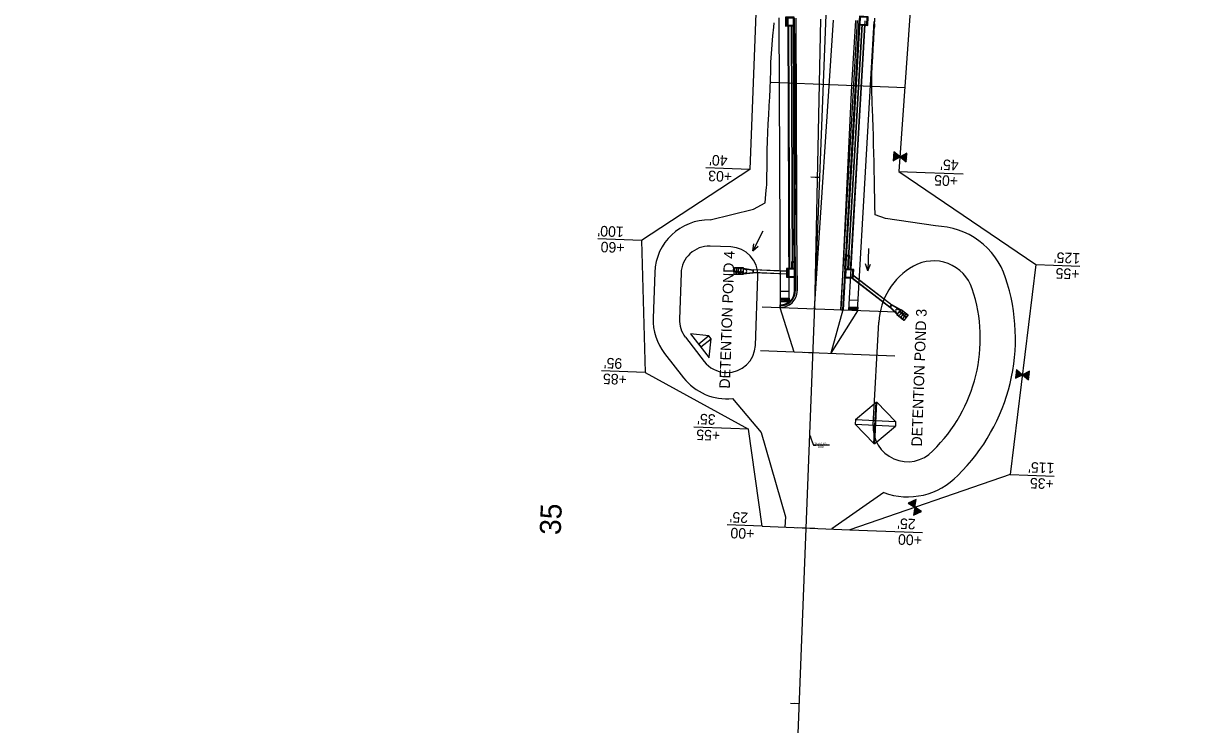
# Model space of a CAD drawing. Extents: x 670017 to 673226, y 705371 to 707498.
# Drawn here: x 671255 to 671926, y 705770 to 706170 of the extents above; entities that cross this region are included whole.
import ezdxf

# ---------------------------------------------------------------- set-up
doc = ezdxf.new("R2010")
doc.units = 0
for name, color, linetype in [('C-STRM-STRC', 7, 'Continuous'), ('EL L SCBV', 7, 'Continuous'), ('EL R SCBV', 7, 'Continuous'), ('R_Drainage Flow Lines', 7, 'Continuous'), ('R_Drainage Stage 1A', 7, 'Continuous'), ('R_Drainage Stage 2', 7, 'Continuous'), ('R_Drainage Stage 2A', 7, 'Continuous'), ('R_Fence', 7, 'Continuous'), ('R_Horz Alg', 7, 'Continuous'), ('R_Horz Alg Station', 7, 'Continuous'), ('R_Horz Alg Station Annot', 7, 'Continuous'), ('R_No Plot', 7, 'Continuous'), ('R_No Plot FOC', 7, 'Continuous'), ('R_Proposed Const Limits Stage 2', 7, 'Continuous'), ('R_Proposed Const Limits Stage 2A', 7, 'Continuous'), ('R_Proposed Road Stage 2', 7, 'Continuous'), ('R_Proposed Road Stage 2A', 7, 'Continuous'), ('R_Proposed Shoulder Stage 2', 7, 'Continuous'), ('R_Proposed Sidewalk Stage 2', 7, 'Continuous'), ('R_Proposed Sidewalk Stage 2A', 7, 'Continuous'), ('R_ROW', 7, 'Continuous'), ('R_ROW Annot', 7, 'Continuous'), ('R_Striping', 7, 'Continuous'), ('R_Water Annot', 7, 'Continuous')]:
    doc.layers.add(name, color=color, linetype=linetype)

# ---------------------------------------------------------------- blocks, each defined once
blk = doc.blocks.new('FLOW ARROW')
at = {"layer": 'R_Water Annot'}
for p, q in [((-12.57, 0), (0, 0)), ((0, 0), (-3.85, 1.4)), ((0, 0), (-3.85, -1.4))]:
    blk.add_line(p, q, dxfattribs=at)
blk = doc.blocks.new('POND 3 STRC')
at = {"layer": 'C-STRM-STRC'}
for points in [[(2047630.3, 2151508), (2047666.7, 2151537.5), (2047668.2, 2151537.4), (2047700.2, 2151503.1)], [(2047661.7, 2151465.8), (2047666.7, 2151537.5)], [(2047663.2, 2151465.7), (2047668.2, 2151537.4)], [(2047630.3, 2151508), (2047629.7, 2151500.1)], [(2047630.3, 2151508), (2047700.2, 2151503.1)], [(2047629.7, 2151500.1), (2047699.7, 2151495.2)], [(2047629.7, 2151500.1), (2047661.7, 2151465.8), (2047663.2, 2151465.7), (2047699.7, 2151495.2)], [(2047700.2, 2151503.1), (2047699.7, 2151495.2)]]:
    blk.add_lwpolyline(points, dxfattribs=at)

msp = doc.modelspace()

# ---------------------------------------------------------------- linework, layer by layer
at = {"layer": 'EL L SCBV'}
msp.add_line((671694.44, 706172.8), (671696.1, 706017.44), dxfattribs=at)
msp.add_arc((671686.6, 706017.49), 9.5, 267.78251, 359.69166, dxfattribs=at)
at = {"layer": 'EL R SCBV'}
for p, q in [((671729.41, 706171.45), (671727.09, 706134.51)), ((671727.09, 706134.51), (671721.03, 706006.65))]:
    msp.add_line(p, q, dxfattribs=at)
at = {"layer": 'R_Drainage Stage 1A'}
for points in [[(671723.31, 706029.87), (671723.69, 706037.86), (671725.68, 706037.76), (671725.31, 706029.77)], [(671723.81, 706029.84), (671724.16, 706037.34), (671725.16, 706037.29), (671724.81, 706029.8)]]:
    msp.add_lwpolyline(points, close=True, dxfattribs=at)
at = {"layer": 'R_Drainage Stage 2'}
for p, q in [((671732.88, 706169.31), (671724.71, 706029.3)), ((671733.05, 706169.3), (671724.88, 706029.29)), ((671734.54, 706169.23), (671726.38, 706029.22)), ((671734.71, 706169.22), (671726.54, 706029.21)), ((671726.68, 706025.2), (671748.93, 706008.08)), ((671726.97, 706025.19), (671749.03, 706008.21)), ((671727.66, 706026.56), (671749.95, 706009.4)), ((671727.67, 706026.76), (671750.05, 706009.53)), ((671748.93, 706008.08), (671749.05, 706008.24)), ((671753.1, 706003.96), (671748.93, 706008.08)), ((671749.05, 706008.24), (671749.93, 706009.37)), ((671749.05, 706008.24), (671749.24, 706008.09)), ((671749.24, 706008.09), (671750.11, 706009.23)), ((671753.22, 706004.12), (671749.25, 706008.11)), ((671749.93, 706009.37), (671750.05, 706009.53)), ((671749.93, 706009.37), (671750.11, 706009.23)), ((671755.1, 706006.55), (671750.05, 706009.53)), ((671754.97, 706006.39), (671750.1, 706009.21)), ((671753.22, 706004.12), (671752.35, 706005.46)), ((671752.35, 706005.46), (671753.1, 706003.96)), ((671753.22, 706004.12), (671753.1, 706003.96)), ((671753.22, 706004.12), (671753.1, 706003.96)), ((671753.22, 706004.12), (671754.97, 706006.39)), ((671754.97, 706006.39), (671753.45, 706006.89)), ((671753.45, 706006.89), (671755.1, 706006.55)), ((671754.97, 706006.39), (671755.1, 706006.55)), ((671754.97, 706006.39), (671755.1, 706006.55))]:
    msp.add_line(p, q, dxfattribs=at)
for points in [[(671736.28, 706168.64), (671736.53, 706173.63), (671731.54, 706173.88), (671731.29, 706168.89)], [(671735.81, 706169.16), (671736.01, 706173.16), (671732.01, 706173.36), (671731.81, 706169.36)], [(671728.07, 706024.64), (671728.3, 706029.63), (671723.31, 706029.87), (671723.07, 706024.87)], [(671727.59, 706025.16), (671727.78, 706029.16), (671723.78, 706029.34), (671723.59, 706025.35)], [(671752.88, 706003.67), (671755.32, 706006.84), (671759.28, 706003.79), (671756.84, 706000.62)]]:
    msp.add_lwpolyline(points, close=True, dxfattribs=at)
msp.add_lwpolyline([(671739.47, 705941.12), (671742.62, 705999.64)], dxfattribs=at)
for centre, radius, start, end in [((671773.79, 706011.23), 23.26, 18.3972, 119.59101), ((671781.56, 705997.54), 39, 119.59101, 176.9246), ((671711.08, 705990.37), 89.35, 314.20485, 18.3972), ((671753.15, 706005.98), 0.957, 71.80174, 213.02684), ((671759.03, 705939.68), 19.61, 175.79284, 317.04539)]:
    msp.add_arc(centre, radius, start, end, dxfattribs=at)
for centre in [(671754.2, 706004.36), (671755.2, 706003.55)]:
    msp.add_ellipse(centre, major_axis=(0.788, 0.971), ratio=0.517889, dxfattribs=at)
for centre, start_param, end_param in [((671755.77, 706006.3), 1.465244, 4.8447), ((671756.13, 706002.63), 3.535072, 9.058057), ((671756.78, 706005.49), 1.438249, 4.871695), ((671757.14, 706001.81), 5.467768, 8.991439), ((671757.14, 706001.81), 3.601691, 4.056701), ((671757.71, 706004.57), 1.309554, 5.00039), ((671758.71, 706003.76), 1.281641, 3.914409)]:
    msp.add_ellipse(centre, major_axis=(0.788, 0.971), ratio=0.517889, start_param=start_param, end_param=end_param, dxfattribs=at)
at = {"layer": 'R_Drainage Stage 2A'}
for p, q in [((671691.04, 706168.81), (671691.63, 706029.67)), ((671691.21, 706168.81), (671691.8, 706029.67)), ((671692.71, 706168.82), (671693.3, 706029.68)), ((671692.88, 706168.82), (671693.47, 706029.68)), ((671665.32, 706030.09), (671665.28, 706027.22)), ((671665.28, 706027.22), (671670.87, 706027.88)), ((671665.28, 706027.22), (671666.8, 706027.74)), ((671666.8, 706027.74), (671665.28, 706027.03)), ((671665.28, 706027.03), (671671.11, 706027.66)), ((671665.32, 706030.09), (671665.33, 706030.29)), ((671665.32, 706030.09), (671665.33, 706030.29)), ((671665.32, 706030.09), (671670.89, 706029.28)), ((671665.32, 706030.09), (671666.83, 706029.54)), ((671665.33, 706030.29), (671671.13, 706029.49)), ((671666.83, 706029.54), (671665.33, 706030.29)), ((671670.89, 706029.3), (671670.87, 706027.86)), ((671671.11, 706027.86), (671670.87, 706027.86)), ((671671.13, 706029.29), (671670.89, 706029.3)), ((671671.13, 706029.29), (671671.11, 706027.86)), ((671671.11, 706027.86), (671671.11, 706027.66)), ((671690.56, 706027.01), (671671.11, 706027.83)), ((671690.56, 706026.84), (671671.11, 706027.66)), ((671671.13, 706029.49), (671671.13, 706029.29)), ((671690.56, 706028.68), (671671.13, 706029.49)), ((671690.56, 706028.51), (671671.13, 706029.33)), ((671665.28, 706027.22), (671665.28, 706027.03)), ((671665.28, 706027.22), (671665.28, 706027.03))]:
    msp.add_line(p, q, dxfattribs=at)
for points in [[(671689.44, 706173.3), (671689.47, 706168.3), (671694.46, 706168.33), (671694.44, 706173.33)], [(671689.94, 706172.8), (671689.96, 706168.8), (671693.96, 706168.82), (671693.94, 706172.82)], [(671665.33, 706030.66), (671665.27, 706026.66), (671660.27, 706026.73), (671660.33, 706030.73)], [(671690.05, 706030.17), (671690.07, 706025.17), (671695.07, 706025.19), (671695.05, 706030.19)], [(671690.55, 706029.67), (671690.57, 706025.67), (671694.57, 706025.69), (671694.55, 706029.69)], [(671693.05, 706030.18), (671693.03, 706034.18), (671695.03, 706034.19), (671695.05, 706030.19)], [(671693.55, 706030.18), (671693.53, 706033.68), (671694.53, 706033.69), (671694.55, 706030.19)]]:
    msp.add_lwpolyline(points, close=True, dxfattribs=at)
for points in [[(671658.29, 706042.42), (671646.51, 706042.84)], [(671629.96, 706027.41), (671629.05, 706001.38)], [(671672.33, 705986.38), (671673.71, 706025.87)], [(671632.4, 705991.02), (671643.14, 705977.16)], [(671645.91, 705979.6), (671647.1, 705990.14), (671645.88, 705991.72), (671635.31, 705992.89)], [(671635.31, 705992.89), (671645.91, 705979.3)], [(671645.88, 705991.72), (671640.01, 705987.04), (671640.62, 705986.25), (671641.24, 705985.46), (671647.1, 705990.14), (671645.88, 705991.72)], [(671655.23, 705970.97), (671655.78, 705970.95)]]:
    msp.add_lwpolyline(points, dxfattribs=at)
for centre, radius, start, end in [((671645.95, 706026.85), 16, 87.99183, 177.99183), ((671657.72, 706026.43), 16, 357.99183, 87.99183), ((671666.5, 706028.64), 0.957, 288.56219, 69.7873), ((671645.04, 706000.82), 16, 177.99183, 217.7949), ((671656.34, 705986.94), 16, 267.99183, 357.99183), ((671655.79, 705986.96), 16, 217.7949, 267.99183)]:
    msp.add_arc(centre, radius, start, end, dxfattribs=at)
for centre, start_param, end_param in [((671660.71, 706027.1), 1.281641, 3.914409), ((671660.81, 706029.6), 5.467768, 8.991439), ((671660.81, 706029.6), 3.601691, 4.056701), ((671662, 706027.05), 1.309554, 5.00039), ((671662.1, 706029.54), 3.535072, 9.058057), ((671663.3, 706026.87), 1.438249, 4.871695), ((671664.59, 706026.82), 1.465244, 4.8447)]:
    msp.add_ellipse(centre, major_axis=(-0.05, -1.25), ratio=0.517889, start_param=start_param, end_param=end_param, dxfattribs=at)
for centre in [(671663.4, 706029.37), (671664.69, 706029.32)]:
    msp.add_ellipse(centre, major_axis=(-0.05, -1.25), ratio=0.517889, dxfattribs=at)
at = {"layer": 'R_Fence'}
for p, q in [((671751.03, 706094.82), (671752.81, 706092.7)), ((671751.09, 706095.53), (671753.26, 706092.94)), ((671751.15, 706096.23), (671753.71, 706093.19)), ((671752.28, 706095.67), (671754.15, 706093.43)), ((671756.84, 706094.91), (671758.4, 706093.04)), ((671757.28, 706095.15), (671758.46, 706093.75)), ((671757.73, 706095.4), (671758.53, 706094.45)), ((671758.18, 706095.64), (671758.59, 706095.16)), ((671758.63, 706095.89), (671758.65, 706095.86)), ((671750.78, 706092.01), (671751.03, 706091.72)), ((671750.85, 706092.71), (671751.47, 706091.96)), ((671750.91, 706093.41), (671751.92, 706092.21)), ((671750.97, 706094.12), (671752.37, 706092.45)), ((671754.27, 706094.08), (671754.6, 706093.68)), ((671755.05, 706093.93), (671756.26, 706092.48)), ((671755.5, 706094.17), (671758.22, 706090.93)), ((671755.94, 706094.42), (671758.28, 706091.63)), ((671756.39, 706094.66), (671758.34, 706092.34)), ((671820.46, 705968.04), (671820.69, 705967.74)), ((671820.54, 705968.74), (671821.15, 705967.98)), ((671820.62, 705969.44), (671821.6, 705968.21)), ((671820.71, 705970.14), (671822.06, 705968.44)), ((671820.79, 705970.85), (671822.51, 705968.67)), ((671820.87, 705971.55), (671822.96, 705968.91)), ((671820.95, 705972.25), (671823.42, 705969.14)), ((671822.06, 705971.66), (671823.87, 705969.37)), ((671824, 705970.01), (671824.33, 705969.6)), ((671824.78, 705969.83), (671825.95, 705968.36)), ((671825.23, 705970.07), (671827.86, 705966.75)), ((671825.69, 705970.3), (671827.94, 705967.45)), ((671826.14, 705970.53), (671828.02, 705968.15)), ((671826.6, 705970.76), (671828.11, 705968.86)), ((671827.05, 705970.99), (671828.19, 705969.56)), ((671827.5, 705971.23), (671828.27, 705970.26)), ((671827.96, 705971.46), (671828.35, 705970.96)), ((671828.41, 705971.69), (671828.43, 705971.66)), ((671759.68, 705896.64), (671759.55, 705896.29)), ((671760.32, 705896.94), (671759.99, 705896.02)), ((671760.96, 705897.23), (671760.42, 705895.76)), ((671761.61, 705897.53), (671760.86, 705895.49)), ((671762.25, 705897.83), (671761.29, 705895.23)), ((671762.89, 705898.13), (671761.73, 705894.96)), ((671763.53, 705898.42), (671762.16, 705894.69)), ((671763.9, 705893.63), (671762.44, 705889.65)), ((671763.6, 705897.17), (671762.6, 705894.43)), ((671763.47, 705893.89), (671762.82, 705892.13)), ((671763.21, 705894.65), (671763.03, 705894.16)), ((671764.34, 705893.36), (671763.09, 705889.95)), ((671764.77, 705893.1), (671763.73, 705890.25)), ((671765.21, 705892.83), (671764.37, 705890.55)), ((671765.64, 705892.56), (671765.01, 705890.84)), ((671766.08, 705892.3), (671765.65, 705891.14)), ((671766.51, 705892.03), (671766.29, 705891.44)), ((671766.95, 705891.77), (671766.94, 705891.74))]:
    msp.add_line(p, q, dxfattribs=at)
for points in [[(671754.71, 706093.74), (671754.69, 706093.74), (671751.18, 706096.55), (671750.75, 706091.57), (671754.69, 706093.73), (671754.7, 706093.73), (671758.22, 706090.92), (671758.65, 706095.9), (671754.71, 706093.74)], [(671824.43, 705969.66), (671824.42, 705969.66), (671820.99, 705972.57), (671820.41, 705967.6), (671824.42, 705969.65), (671824.43, 705969.65), (671827.86, 705966.74), (671828.44, 705971.7), (671824.43, 705969.66)], [(671763.13, 705894.1), (671763.13, 705894.11), (671763.82, 705898.56), (671759.28, 705896.46), (671763.12, 705894.11), (671763.12, 705894.1), (671762.43, 705889.65), (671766.97, 705891.75), (671763.13, 705894.1)]]:
    msp.add_lwpolyline(points, dxfattribs=at)
at = {"layer": 'R_Horz Alg'}
msp.add_line((671681.86, 705382.69), (671726.73, 706541.35), dxfattribs=at)
at = {"layer": 'R_Horz Alg Station'}
for points in [[(671703.95, 706082.36), (671708.94, 706082.17)], [(671706.45, 706082.27), (671708.94, 706082.17)], [(671700.08, 705982.44), (671705.08, 705982.25)], [(671702.58, 705982.34), (671705.08, 705982.25)], [(671696.21, 705882.51), (671706.2, 705882.13)], [(671696.21, 705882.51), (671706.2, 705882.13)], [(671692.34, 705782.59), (671697.34, 705782.4)], [(671694.84, 705782.49), (671697.34, 705782.4)]]:
    msp.add_lwpolyline(points, dxfattribs=at)
at = {"layer": 'R_No Plot'}
msp.add_line((671714.55, 705929.47), (671706.66, 705929.47), dxfattribs=at)
for points in [[(671681.2, 706136.28), (671757.61, 706133.33)], [(671676.24, 706008.38), (671752.66, 706005.42)], [(671675.28, 705983.4), (671751.69, 705980.44)], [(671703.24, 705934.91), (671705.46, 705929.47), (671706.66, 705929.47)]]:
    msp.add_lwpolyline(points, dxfattribs=at)
msp.add_lwpolyline([(671703.24, 705934.91), (671703.95, 705933.94), (671703.41, 705933.72)], close=True, dxfattribs=at)
at = {"layer": 'R_No Plot FOC'}
for p, q in [((671695.1, 706017.42), (671694.44, 706172.8)), ((671722.03, 706006.59), (671731.41, 706171.37))]:
    msp.add_line(p, q, dxfattribs=at)
msp.add_arc((671686.6, 706017.49), 8.5, 267.78251, 359.69166, dxfattribs=at)
at = {"layer": 'R_Proposed Const Limits Stage 2'}
msp.add_line((671745.41, 705902.49), (671715.78, 705881.76), dxfattribs=at)
msp.add_lwpolyline([(671774.91, 706054.38), (671746.48, 706058.73), (671740.53, 706060.79), (671740.42, 706065.8), (671740.31, 706070.81), (671740.23, 706074.76), (671740.21, 706075.82), (671740.12, 706080.83), (671740.03, 706085.84), (671739.94, 706090.85), (671739.8, 706095.86), (671739.67, 706100.87), (671739.67, 706101.01), (671739.55, 706105.89), (671739.36, 706110.9), (671739.19, 706115.91), (671739.02, 706120.93), (671738.92, 706123.88), (671738.85, 706125.94), (671738.69, 706130.95), (671738.64, 706135.48), (671738.69, 706140.5), (671738.89, 706145.51), (671739.14, 706150.51), (671739.41, 706155.35), (671739.42, 706155.52), (671739.69, 706160.52), (671739.97, 706165.52), (671740.1, 706167.92), (671740.13, 706168.37), (671740.13, 706168.52), (671740.19, 706169.52), (671740.19, 706167.68), (671740.22, 706168.13), (671740.23, 706168.45), (671740.35, 706172.72)], dxfattribs=at)
for centre, radius, start, end in [((671774.14, 706011.55), 42.83, 18.1334, 88.96673), ((671711.08, 705990.37), 109.35, 314.43226, 18.3972), ((671759.03, 705939.68), 39.61, 249.88802, 316.23878)]:
    msp.add_arc(centre, radius, start, end, dxfattribs=at)
at = {"layer": 'R_Proposed Const Limits Stage 2A'}
for points in [[(671646.53, 706057.84), (671671.29, 706063.97), (671677.93, 706067.59), (671678.34, 706072.59), (671678.67, 706076.55), (671678.74, 706077.6), (671678.84, 706082.61), (671678.93, 706087.61), (671679.01, 706092.62), (671679.08, 706097.62), (671679.15, 706102.63), (671679.15, 706102.76), (671679.37, 706107.63), (671679.66, 706112.64), (671679.93, 706117.64), (671680.2, 706122.65), (671680.36, 706125.6), (671680.44, 706127.66), (671680.64, 706132.66), (671680.82, 706137.67), (671681.01, 706142.67), (671681.18, 706147.68), (671681.39, 706152.68), (671681.82, 706157.53), (671681.84, 706157.69), (671682.29, 706162.7), (671682.73, 706167.7), (671682.95, 706170.11)], [(671614.97, 706027.93), (671614.06, 706001.91)], [(671620.54, 705981.82), (671631.29, 705967.96)], [(671659.28, 705956.06), (671675.53, 705936.67), (671689.42, 705888.74), (671689.04, 705882.79)]]:
    msp.add_lwpolyline(points, dxfattribs=at)
for centre, radius, start, end in [((671645.95, 706026.85), 31, 88.92965, 177.99183), ((671645.04, 706000.82), 31, 177.99183, 217.7949), ((671656.12, 705987.48), 31.58, 218.17056, 275.74216)]:
    msp.add_arc(centre, radius, start, end, dxfattribs=at)
at = {"layer": 'R_Proposed Road Stage 2'}
for p, q in [((671721.03, 706006.65), (671730.41, 706171.42)), ((671722.53, 706006.56), (671731.91, 706171.35)), ((671722.03, 706006.61), (671715.37, 705981.83)), ((671721.03, 706006.65), (671722.53, 706006.59))]:
    msp.add_line(p, q, dxfattribs=at)
at = {"layer": 'R_Proposed Road Stage 2A'}
for p, q in [((671694.6, 706017.42), (671693.94, 706172.82)), ((671696.1, 706017.44), (671695.44, 706172.76)), ((671686.29, 706009.49), (671686.24, 706007.99)), ((671686.24, 706007.99), (671694.3, 705982.66))]:
    msp.add_line(p, q, dxfattribs=at)
for radius in [9.5, 8]:
    msp.add_arc((671686.6, 706017.49), radius, 267.78251, 359.69166, dxfattribs=at)
at = {"layer": 'R_Proposed Shoulder Stage 2'}
msp.add_line((671730.52, 706006.11), (671715.37, 705981.83), dxfattribs=at)
at = {"layer": 'R_Proposed Sidewalk Stage 2'}
for p, q in [((671725.52, 706006.39), (671734.91, 706171.18)), ((671730.52, 706006.11), (671739.9, 706170.9)), ((671725.87, 706012.38), (671730.86, 706012.1))]:
    msp.add_line(p, q, dxfattribs=at)
msp.add_lwpolyline([(671730.52, 706006.11), (671725.52, 706006.39), (671725.64, 706008.39), (671730.63, 706008.1)], close=True, dxfattribs=at)
for centre in [(671725.98, 706007.37), (671726.01, 706007.97), (671726.61, 706007.93), (671727.21, 706007.9), (671727.81, 706007.86), (671728.41, 706007.83), (671729.01, 706007.79), (671729.61, 706007.76), (671730.21, 706007.73), (671725.95, 706006.77), (671726.55, 706006.73), (671726.58, 706007.33), (671727.14, 706006.7), (671727.18, 706007.3), (671727.74, 706006.66), (671727.78, 706007.26), (671728.34, 706006.63), (671728.38, 706007.23), (671728.94, 706006.6), (671728.98, 706007.2), (671729.54, 706006.56), (671729.57, 706007.16), (671730.14, 706006.53), (671730.17, 706007.13)]:
    msp.add_circle(centre, 0.165, dxfattribs=at)
at = {"layer": 'R_Proposed Sidewalk Stage 2A'}
for p, q in [((671686.64, 706007.99), (671685.94, 706172.96)), ((671691.64, 706009.43), (671690.94, 706172.87)), ((671686.6, 706017.24), (671691.6, 706017.26))]:
    msp.add_line(p, q, dxfattribs=at)
msp.add_lwpolyline([(671691.63, 706011.26), (671686.63, 706011.24), (671686.62, 706013.24), (671691.62, 706013.26)], close=True, dxfattribs=at)
for centre in [(671687.02, 706012.84), (671687.03, 706012.24), (671687.03, 706011.64), (671687.62, 706012.85), (671687.63, 706012.25), (671687.63, 706011.65), (671688.22, 706012.85), (671688.23, 706012.25), (671688.23, 706011.65), (671688.82, 706012.85), (671688.83, 706012.25), (671688.83, 706011.65), (671689.42, 706012.85), (671689.43, 706012.25), (671689.43, 706011.65), (671690.02, 706012.86), (671690.03, 706012.26), (671690.03, 706011.66), (671690.62, 706012.86), (671690.63, 706012.26), (671690.63, 706011.66), (671691.22, 706012.86), (671691.23, 706012.26), (671691.23, 706011.66)]:
    msp.add_circle(centre, 0.165, dxfattribs=at)
at = {"layer": 'R_ROW'}
for p, q in [((671676.23, 705883.29), (671668.36, 705938.63)), ((671676.23, 705883.29), (671726.19, 705881.35)), ((671726.19, 705881.35), (671726.19, 705881.35))]:
    msp.add_line(p, q, dxfattribs=at)
for points in [[(670759.59, 706562.46), (670811.11, 706494.67), (670891, 706490.47), (670958.53, 706537), (671303.32, 706523.91), (671422.37, 706502.64), (671542.46, 706501.35), (671626.3, 706476.92), (671666.37, 706404.06), (671678.47, 706328.82), (671669.08, 706086.55), (671607.47, 706046.07), (671609.57, 705970.93), (671668.36, 705938.63)], [(672596.28, 706451.05), (672596.28, 706451.05), (672161.7, 706463.84), (671891.46, 706473.02), (671825.24, 706451.46), (671776.29, 706399.8), (671754.1, 706085.43), (671832.11, 706032.37), (671817.47, 705912.84), (671726.19, 705881.35)]]:
    msp.add_lwpolyline(points, dxfattribs=at)
at = {"layer": 'R_ROW Annot'}
for points in [[(671669.08, 706086.55), (671654.1, 706087.13), (671644.1, 706087.52)], [(671754.1, 706085.43), (671769.09, 706084.85), (671790.76, 706084.01)], [(671607.47, 706046.07), (671597.48, 706046.46), (671582.49, 706047.04)], [(671832.11, 706032.37), (671842.1, 706031.98), (671857.09, 706031.4)], [(671609.57, 705970.93), (671599.57, 705971.32), (671584.59, 705971.9)], [(671668.36, 705938.63), (671658.37, 705939.02), (671637.27, 705939.84)], [(671817.47, 705912.84), (671827.47, 705912.46), (671842.46, 705911.88)], [(671676.23, 705883.29), (671671.23, 705883.48), (671656.24, 705884.06)], [(671726.19, 705881.35), (671741.28, 705880.76), (671767.5, 705879.73)]]:
    msp.add_lwpolyline(points, dxfattribs=at)
at = {"layer": 'R_Striping'}
for p, q in [((671709.43, 706172.22), (671706.04, 706007.23)), ((671706.04, 706007.23), (671716.72, 706171.57))]:
    msp.add_line(p, q, dxfattribs=at)

# ---------------------------------------------------------------- block references
at = {"layer": 'R_Drainage Flow Lines'}
for p, rotation in [((671670.92, 706040.13), -116.5183132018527), ((671736.28, 706028.92), -92.21751391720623)]:
    msp.add_blockref('FLOW ARROW', p, dxfattribs=dict(at, rotation=rotation))
at = {"layer": 'R_Drainage Stage 2', "xscale": 0.32808333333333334, "yscale": 0.3280833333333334, "rotation": 0.9042568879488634}
msp.add_blockref('POND 3 STRC', (11159.37, -10443.84), dxfattribs=at)

# ---------------------------------------------------------------- texts
at = {"layer": 'R_Horz Alg Station Annot'}
msp.add_text('35', height=12, rotation=87.78251, dxfattribs=at).set_placement((671561.39, 705878.18))
at = {"layer": 'R_No Plot'}
for s, p in [('35+52.63', (671705.79, 705929.77)), ('0.00', (671707.87, 705927.97))]:
    msp.add_text(s, height=1.2, rotation=360, dxfattribs=at).set_placement(p)
at = {"layer": 'R_ROW Annot'}
for s, rotation, p in [("40'", 177.78251, (671656.58, 706094.54)), ("45'", 177.78251, (671788.2, 706091.95)), ('+03', 177.78251, (671659.16, 706085.43)), ('+05', 177.78251, (671787.85, 706082.96)), ("100'", 177.78251, (671597.42, 706053.96)), ('+60', 177.78251, (671597.88, 706044.94)), ('DETENTION POND 4', 87.98493, (671657.71, 705961.65)), ("125'", 177.78251, (671857.38, 706038.89)), ('+55', 177.78251, (671857.03, 706029.9)), ('DETENTION POND 3', 87.98493, (671767.14, 705928.65)), ("95'", 177.78251, (671596.58, 705978.94)), ('+85', 177.78251, (671599.17, 705969.83)), ("35'", 177.78251, (671649.75, 705947.05)), ('+55', 177.78251, (671652.34, 705937.95)), ("115'", 177.78251, (671842.75, 705919.37)), ('+35', 177.78251, (671842.4, 705910.38)), ("25'", 177.78251, (671668.24, 705891.1)), ("25'", 177.74704, (671763.7, 705887.46)), ('+00', 177.78251, (671671.82, 705881.96)), ('+00', 177.74704, (671767.27, 705878.31))]:
    msp.add_text(s, height=6, rotation=rotation, dxfattribs=at).set_placement(p)

doc.saveas('drawing.dxf')
